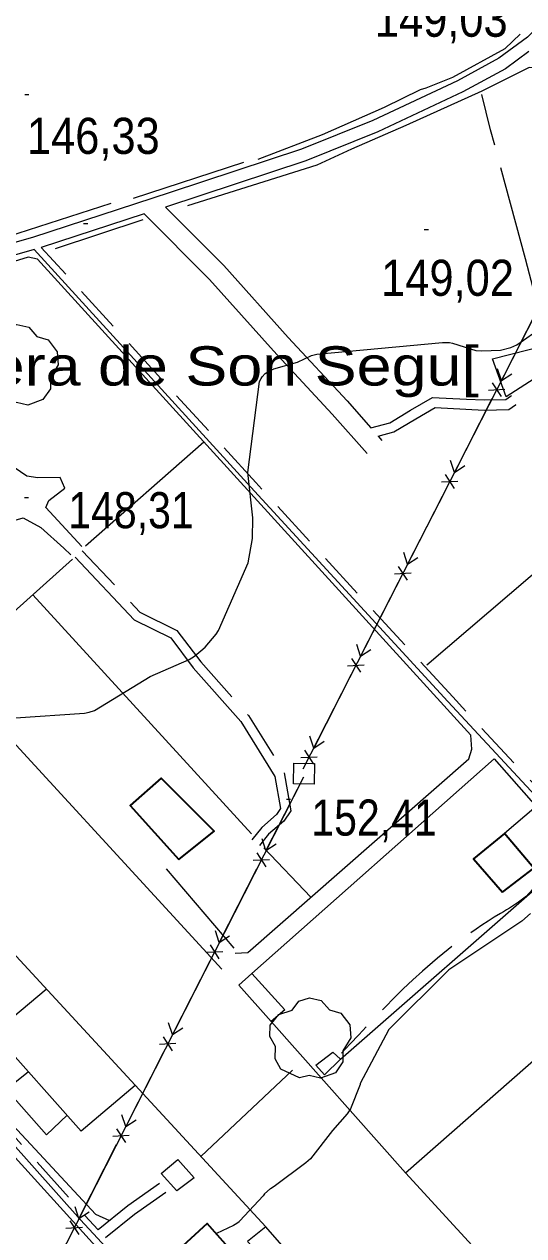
# Model space of a CAD drawing. Extents: x 480269 to 484877, y 4383588 to 4386804.
# Drawn here: x 481631.7 to 481752.8, y 4385501.1 to 4385794.6 of the extents above; entities that cross this region are included whole.
import ezdxf
from ezdxf.enums import TextEntityAlignment as Align

# ---------------------------------------------------------------- set-up
doc = ezdxf.new("R2010")
doc.units = 0
doc.header["$LTSCALE"] = 3.8
doc.linetypes.add('LONG_DASHED', pattern=[7.5, 6, -1.5])
doc.linetypes.add('MEDIUM_DASHED', pattern=[4.5, 3, -1.5])
for name, color, linetype, lineweight in [('21', 7, 'Continuous', 25), ('25', 7, 'LONG_DASHED', 25), ('29', 7, 'Continuous', 13), ('38', 7, 'Continuous', 25), ('43', 7, 'Continuous', 25), ('47', 7, 'Continuous', 35), ('51', 7, 'Continuous', 13), ('7', 7, 'Continuous', 13), ('8', 7, 'Continuous', 25), ('9', 7, 'Continuous', 13)]:
    doc.layers.add(name, color=color, linetype=linetype, lineweight=lineweight)
doc.layers.add('5', color=7, linetype='Continuous')

msp = doc.modelspace()

# ---------------------------------------------------------------- linework, layer by layer
at = {"layer": '21'}
msp.add_lwpolyline([(481748.51, 4385704.39), (481745.18, 4385713.54), (481758.21, 4385716.84), (481756.48, 4385709.48)], close=True, dxfattribs=at)
at = {"layer": '25'}
msp.add_lwpolyline([(481758.38, 4385718), (481753.24, 4385737.83), (481744.74, 4385769.08), (481742.6, 4385777.57)], dxfattribs=at)
at = {"layer": '29'}
for points in [[(481627.49, 4385702.45), (481622.95, 4385704.57), (481621.54, 4385707.11), (481621.64, 4385710.09), (481620.27, 4385712.5), (481620.31, 4385715.25), (481622.47, 4385717.85), (481625.66, 4385718.85), (481627.31, 4385721.04), (481629.88, 4385721.87), (481632.74, 4385721.22), (481634.69, 4385718.95), (481637.5, 4385718.13), (481639.63, 4385715.28), (481639.87, 4385712.15), (481637.99, 4385709), (481637.99, 4385706.32), (481636.17, 4385703.71), (481632.55, 4385702.37), (481629.78, 4385703)], [(481698.45, 4385539.37), (481693.91, 4385541.49), (481692.5, 4385544.03), (481692.6, 4385547.01), (481691.23, 4385549.42), (481691.27, 4385552.17), (481693.43, 4385554.77), (481696.62, 4385555.77), (481698.27, 4385557.96), (481700.84, 4385558.79), (481703.7, 4385558.14), (481705.65, 4385555.87), (481708.46, 4385555.05), (481710.59, 4385552.2), (481710.83, 4385549.07), (481708.95, 4385545.92), (481708.95, 4385543.24), (481707.13, 4385540.63), (481703.51, 4385539.29), (481700.74, 4385539.92)]]:
    msp.add_lwpolyline(points, close=True, dxfattribs=at)
at = {"layer": '38'}
for p, q in [((481660.77, 4385748.67), (481635.79, 4385740.57)), ((481717.53, 4385694.82), (481718.42, 4385693.82))]:
    msp.add_line(p, q, dxfattribs=at)
for points in [[(481760.24, 4385798.16), (481753.7, 4385791.52), (481746.77, 4385786.38), (481736.7, 4385780.94), (481716.23, 4385771.32), (481698.91, 4385764.33), (481667.07, 4385753.84), (481633.65, 4385743), (481600.45, 4385733.48), (481585.31, 4385727.58), (481572.78, 4385722.51), (481566.04, 4385718.67), (481547.68, 4385711.16)], [(481754.03, 4385788.04), (481748.38, 4385783.86), (481738.04, 4385778.28), (481717.42, 4385768.58), (481699.93, 4385761.53), (481665.95, 4385750.34)], [(481660.77, 4385748.67), (481676.57, 4385732.8), (481692.11, 4385715.5), (481706.35, 4385700.13), (481714.79, 4385690.6)], [(481665.95, 4385750.34), (481680.1, 4385736.14), (481695.7, 4385718.77), (481709.95, 4385703.39), (481715.74, 4385696.85)], [(481634.09, 4385740.02), (481601.4, 4385730.65), (481591.06, 4385726.63)], [(481785.86, 4385576.27), (481772.58, 4385589.56), (481734.37, 4385630.55), (481686.64, 4385682.48), (481634.09, 4385740.02)], [(481645.62, 4385668.1), (481636.92, 4385677.56), (481637.63, 4385679.23), (481641.53, 4385682.25), (481640.38, 4385684.84), (481634.95, 4385684.73), (481632.26, 4385685.17), (481627.89, 4385688.13), (481624.4, 4385691.43), (481620.48, 4385694.8), (481616.44, 4385698.72), (481614.68, 4385701.28), (481612.25, 4385705.5), (481607.31, 4385709.27), (481603.73, 4385711.12), (481600, 4385715.03), (481596.04, 4385718.41), (481592.81, 4385721.6), (481590.93, 4385724.66), (481590.87, 4385726.2), (481591.06, 4385726.63)], [(481715.74, 4385696.85), (481720.32, 4385698.1), (481725.37, 4385701.12), (481730.68, 4385704.2), (481738.91, 4385703.8), (481743.23, 4385703.6), (481748.42, 4385703.72), (481749.56, 4385704.51), (481749.84, 4385704.66)], [(481623.19, 4385665.01), (481626.59, 4385670.78), (481629.45, 4385674.49), (481631.38, 4385675.08), (481635.7, 4385672.74), (481641.29, 4385667.74), (481642.94, 4385666.05)], [(481498.09, 4385665.9), (481507.46, 4385656.61), (481535.39, 4385625.76), (481568.02, 4385590.29), (481598.94, 4385556.93), (481622.28, 4385530.75), (481645.27, 4385505), (481666.95, 4385481.63), (481678.43, 4385469.2)], [(481644.01, 4385665.5), (481658.33, 4385650.3), (481667.18, 4385645.95), (481672.66, 4385638.69), (481684.19, 4385625.74), (481692.47, 4385612.42), (481693.84, 4385604.63), (481692.83, 4385603.16), (481689.25, 4385600.06), (481686.87, 4385597.08)], [(481664.47, 4385513.8), (481656.81, 4385508.4), (481649.57, 4385502.55)]]:
    msp.add_lwpolyline(points, dxfattribs=at)
at = {"layer": '38', "linetype": 'MEDIUM_DASHED'}
for points in [[(481841.36, 4385571.14), (481829.38, 4385568.4), (481820.77, 4385568.33), (481810.17, 4385570.08), (481797.29, 4385573.9), (481786.27, 4385578.16), (481773.75, 4385590.69), (481735.56, 4385631.66), (481687.84, 4385683.57), (481635.79, 4385740.57)], [(481717.53, 4385694.82), (481721.28, 4385695.85), (481726.6, 4385699.03), (481731.28, 4385701.74), (481738.79, 4385701.38), (481743.2, 4385701.17), (481749.2, 4385701.31), (481750.83, 4385702.44), (481750.98, 4385702.52)], [(481499.28, 4385666.8), (481508.54, 4385657.65), (481536.49, 4385626.76), (481569.12, 4385591.3), (481600.04, 4385557.93), (481623.39, 4385531.74), (481646.37, 4385506), (481649.57, 4385502.55)], [(481645.7, 4385667.09), (481659.73, 4385652.19), (481668.7, 4385647.78), (481674.45, 4385640.17), (481686.06, 4385627.14), (481694.67, 4385613.26), (481696.29, 4385604.1), (481694.58, 4385601.6), (481690.93, 4385598.45), (481688.68, 4385595.64)], [(481666.01, 4385511.62), (481658.42, 4385506.27), (481651.4, 4385500.59)]]:
    msp.add_lwpolyline(points, dxfattribs=at)
at = {"layer": '38', "linetype": 'LONG_DASHED'}
msp.add_spline([(481756.26, 4385589.23), (481756.1, 4385587.78), (481747.14, 4385579.2), (481708.6, 4385545.33)], degree=3, dxfattribs=at)
at = {"layer": '43'}
for p, q in [((481995.46, 4386193.59), (481699.21, 4385614.13)), ((481756.47, 4385726.14), (481747.37, 4385708.33)), ((481747.37, 4385708.33), (481746.45, 4385711.18)), ((481745.14, 4385707.79), (481747.31, 4385704.43)), ((481747.37, 4385708.33), (481749.89, 4385709.96)), ((481744.23, 4385706.01), (481748.22, 4385706.21)), ((481745.09, 4385703.88), (481735.99, 4385686.07)), ((481735.99, 4385686.07), (481735.07, 4385688.92)), ((481735.99, 4385686.07), (481738.51, 4385687.7)), ((481733.76, 4385685.53), (481735.93, 4385682.17)), ((481733.71, 4385681.62), (481724.61, 4385663.81)), ((481732.85, 4385683.75), (481736.84, 4385683.95)), ((481724.61, 4385663.81), (481723.69, 4385666.66)), ((481724.61, 4385663.81), (481727.13, 4385665.44)), ((481721.47, 4385661.49), (481725.46, 4385661.69)), ((481722.38, 4385663.27), (481724.55, 4385659.91)), ((481722.33, 4385659.36), (481713.23, 4385641.55)), ((481713.23, 4385641.55), (481712.31, 4385644.4)), ((481713.23, 4385641.55), (481715.75, 4385643.18)), ((481711, 4385641.01), (481713.17, 4385637.65)), ((481710.95, 4385637.1), (481701.85, 4385619.29)), ((481710.09, 4385639.23), (481714.08, 4385639.43)), ((481701.85, 4385619.29), (481700.93, 4385622.15)), ((481701.85, 4385619.29), (481704.37, 4385620.92)), ((481698.71, 4385616.97), (481702.7, 4385617.17)), ((481699.62, 4385618.75), (481701.79, 4385615.39)), ((481699.57, 4385614.84), (481699.21, 4385614.13)), ((481699.35, 4385612.25), (481294.48, 4384816.83)), ((481699.35, 4385612.25), (481690.28, 4385594.43)), ((481690.28, 4385594.43), (481689.35, 4385597.28)), ((481690.28, 4385594.43), (481692.79, 4385596.06)), ((481688.05, 4385593.88), (481690.22, 4385590.53)), ((481687.14, 4385592.1), (481691.13, 4385592.31)), ((481688.01, 4385589.97), (481678.94, 4385572.15)), ((481678.94, 4385572.15), (481678.01, 4385575)), ((481678.94, 4385572.15), (481681.45, 4385573.78)), ((481675.8, 4385569.82), (481679.79, 4385570.03)), ((481676.71, 4385571.6), (481678.88, 4385568.25)), ((481676.67, 4385567.69), (481667.6, 4385549.87)), ((481667.6, 4385549.87), (481666.67, 4385552.72)), ((481665.37, 4385549.32), (481667.54, 4385545.97)), ((481667.6, 4385549.87), (481670.11, 4385551.5)), ((481664.46, 4385547.54), (481668.45, 4385547.75)), ((481665.33, 4385545.41), (481656.26, 4385527.59)), ((481656.26, 4385527.59), (481655.33, 4385530.44)), ((481656.26, 4385527.59), (481658.77, 4385529.22)), ((481654.03, 4385527.04), (481656.2, 4385523.69)), ((481653.99, 4385523.13), (481644.92, 4385505.31)), ((481653.12, 4385525.26), (481657.11, 4385525.47)), ((481644.92, 4385505.31), (481643.99, 4385508.16)), ((481644.92, 4385505.31), (481647.43, 4385506.94)), ((481641.78, 4385502.98), (481645.77, 4385503.19)), ((481642.68, 4385504.76), (481644.86, 4385501.41))]:
    msp.add_line(p, q, dxfattribs=at)
at = {"layer": '43', "lineweight": 13}
msp.add_lwpolyline([(481697.05, 4385615.64), (481702.05, 4385615.54), (481701.95, 4385610.54), (481696.95, 4385610.64)], close=True, dxfattribs=at)
at = {"layer": '47'}
for points in [[(481669.19, 4385592.27), (481677.69, 4385599.18), (481664.9, 4385611.97), (481657.31, 4385605.37)], [(481747.65, 4385584.36), (481755.26, 4385590.21), (481748.11, 4385598.57), (481740.62, 4385592.47)], [(481676.69, 4385487.38), (481684.86, 4385494.2), (481676.04, 4385504.13), (481668.1, 4385496.8)]]:
    msp.add_lwpolyline(points, close=True, dxfattribs=at)
at = {"layer": '47', "lineweight": 13}
for points in [[(481683.73, 4385561.84), (481686.83, 4385564.7), (481694.86, 4385555.9), (481691.55, 4385553.03)], [(481704.48, 4385540.15), (481702.38, 4385542.42), (481706.47, 4385545.59), (481708.37, 4385543.89)], [(481672.85, 4385515.2), (481668.67, 4385512.03), (481664.84, 4385516.24), (481668.89, 4385519.63)], [(481690.1, 4385495.12), (481694.11, 4385498.83), (481690.22, 4385503.28), (481685.83, 4385499.71)]]:
    msp.add_lwpolyline(points, close=True, dxfattribs=at)
at = {"layer": '51'}
for p, q in [((481658.17, 4385752.49), (481684.94, 4385761.17)), ((481587.46, 4385730.22), (481652.73, 4385751.27)), ((481660.41, 4385747.26), (481639.16, 4385740.21)), ((481646.51, 4385668.25), (481675.23, 4385693.45)), ((481729.28, 4385639.46), (481765.98, 4385670.8)), ((481613.14, 4385637.96), (481643.38, 4385665.02)), ((481633.78, 4385656.43), (481686.77, 4385598.5)), ((481689.75, 4385595.14), (481701.2, 4385583.17)), ((481666.05, 4385590.04), (481682.52, 4385570.79)), ((481708.37, 4385543.89), (481759.59, 4385588.74)), ((481696.7, 4385541.24), (481674.48, 4385520.31))]:
    msp.add_line(p, q, dxfattribs=at)
for points in [[(481688.41, 4385761.94), (481704.02, 4385767.9), (481719.04, 4385774.57), (481727.73, 4385778.78), (481729.13, 4385779.25), (481735.57, 4385781.8), (481748.3, 4385788.78), (481751.93, 4385792.18)], [(481785.02, 4385732.31), (481757.89, 4385783.94), (481754.14, 4385784.16), (481742.63, 4385778.43)], [(481742.63, 4385778.43), (481724.22, 4385770.07), (481710.99, 4385764.36), (481702.64, 4385760.46), (481671.27, 4385750.67)], [(481682.83, 4385569.62), (481685.86, 4385569.76), (481739.52, 4385616.65), (481740.23, 4385619.04), (481740, 4385622.39), (481634.85, 4385737.74), (481632.64, 4385738.19), (481592.21, 4385725.73), (481592.29, 4385723.01)], [(481690.22, 4385503.28), (481622.89, 4385576.1), (481525.44, 4385682.64), (481502.51, 4385665.98)], [(481679.54, 4385565.75), (481613.3, 4385637.77), (481579.05, 4385675.82)], [(481499.22, 4385663.05), (481597.3, 4385555.43), (481657.55, 4385489.12), (481765.67, 4385373.25), (481745.31, 4385335.89)], [(481686.83, 4385564.7), (481745.65, 4385616.66), (481755.79, 4385605.09), (481748.11, 4385598.57)], [(481757.42, 4385599.72), (481760.3, 4385600.77), (481786.96, 4385571.33), (481724.16, 4385516.33)], [(481652.41, 4385504.77), (481649.04, 4385506.26), (481615.13, 4385542.58), (481637, 4385560.85)], [(481765.67, 4385373.25), (481798.4, 4385435.49), (481724.13, 4385516.36), (481691.55, 4385553.03)], [(481658.54, 4385537.55), (481645.5, 4385526.51), (481624.28, 4385550.22)], [(481632.68, 4385540.84), (481627.37, 4385536.54), (481637.02, 4385525.57), (481642.04, 4385530.38)]]:
    msp.add_lwpolyline(points, dxfattribs=at)
at = {"layer": '7'}
for p, q in [((481631.81, 4385777.58), (481632.81, 4385777.58)), ((481646.05, 4385746.32), (481647.05, 4385746.32)), ((481728.66, 4385744.87), (481729.66, 4385744.87)), ((481631.69, 4385679.97), (481632.69, 4385679.97)), ((481695.27, 4385606.92), (481696.27, 4385606.92))]:
    msp.add_line(p, q, dxfattribs=at)
at = {"layer": '8'}
msp.add_lwpolyline([(481629.57, 4385626.64), (481646.26, 4385627.73), (481647.38, 4385627.97), (481648.67, 4385628.41), (481662.16, 4385636.6), (481671.62, 4385640.71), (481672.99, 4385641.53), (481675.5, 4385643.68), (481678.17, 4385646.86), (481678.78, 4385647.77), (481685.98, 4385664.18), (481687.05, 4385670.03), (481687.1, 4385675.05), (481685.86, 4385686.02), (481688.75, 4385708.07), (481689.11, 4385708.82), (481689.4, 4385709.23), (481690.09, 4385709.99), (481691.26, 4385710.72), (481692.22, 4385711.12), (481697.95, 4385712.8), (481701.29, 4385714.36), (481702.63, 4385714.7), (481733.07, 4385717.56), (481734.8, 4385717.49), (481735.51, 4385717.4), (481741.16, 4385715.6), (481742.63, 4385715.48), (481747.14, 4385715.7), (481749.7, 4385716.31), (481751.16, 4385716.97), (481757.34, 4385721.29)], dxfattribs=at)
at = {"layer": '9'}
msp.add_lwpolyline([(481754.45, 4385579.24), (481752.37, 4385577.31), (481734.6, 4385565.53), (481720.11, 4385551.12), (481713.1, 4385537.99), (481713.1, 4385537.97), (481713.12, 4385537.8), (481710.76, 4385531.92), (481709.97, 4385530.7), (481706.38, 4385526.64), (481701.05, 4385519.78), (481699.99, 4385518.78), (481692.26, 4385513.06), (481691.38, 4385512.54), (481691.27, 4385512.47), (481689.95, 4385511.3), (481689.57, 4385510.81), (481683.94, 4385504.76), (481683.93, 4385504.74), (481683.9, 4385504.65), (481683.78, 4385504.52), (481683.23, 4385504.08), (481682.41, 4385503.59), (481678.25, 4385501.64)], dxfattribs=at)

# ---------------------------------------------------------------- texts
at = {"layer": '5', "width": 1.2}
msp.add_text('Teulera de Son Segu[', height=9.5, dxfattribs=at).set_placement((481741.94, 4385707.1), align=Align.RIGHT)
at = {"layer": '7'}
for s, width, p in [('149,03', 0.9, (481716.69, 4385791.59)), ('146,33', 0.9, (481632.31, 4385763.21)), ('149,02', 0.9, (481718.21, 4385728.82)), ('148,31', 0.85, (481642.34, 4385672.53)), ('152,41', 0.85, (481701.28, 4385598.06))]:
    msp.add_text(s, height=8.75, dxfattribs=dict(at, width=width)).set_placement(p)

doc.saveas('drawing.dxf')
